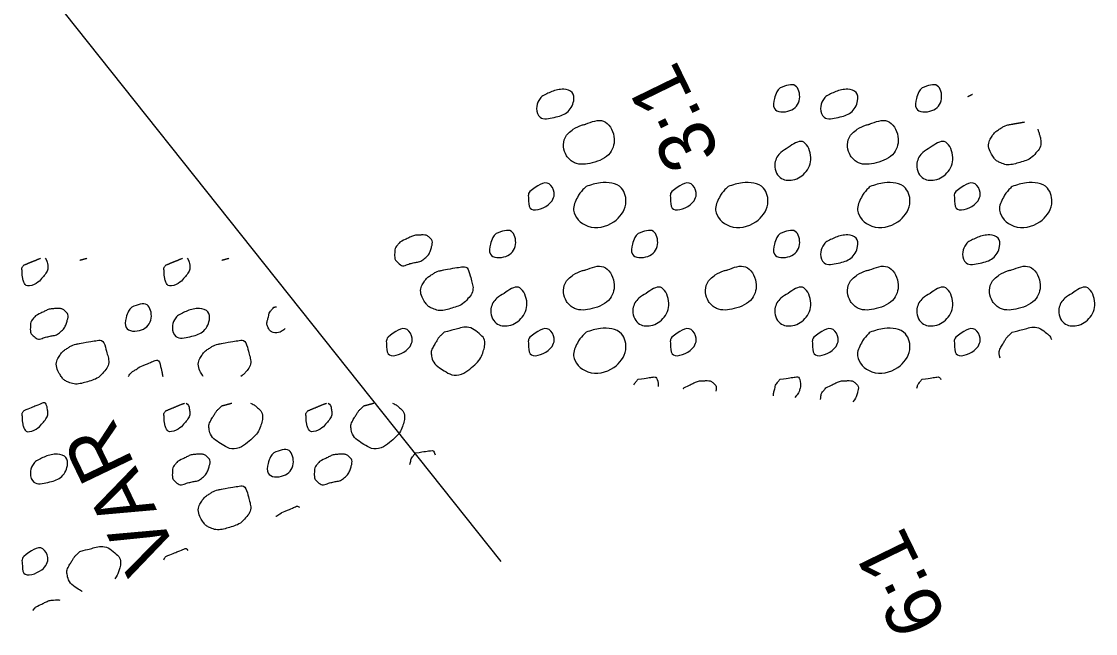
# Model space of a CAD drawing. Extents: x 0 to 2278, y -264 to 330.
# Drawn here: x 114.06 to 154.18, y 221.76 to 244.64 of the extents above; entities that cross this region are included whole.
import ezdxf

# ---------------------------------------------------------------- set-up
doc = ezdxf.new("R2010")
doc.units = 0
doc.layers.add('DR_P_Culvert', color=7, linetype='Continuous')
doc.layers.add('XS_P_Finished_Grade', color=7, linetype='Continuous')

msp = doc.modelspace()

# ---------------------------------------------------------------- linework, layer by layer
at = {"layer": 'DR_P_Culvert'}
msp.add_line((131.975, 224.45), (97.773, 267.515), dxfattribs=at)
at = {"layer": 'XS_P_Finished_Grade'}
for points in [[(142.395, 242.152), (142.967, 242.235), (143.124, 241.743), (142.764, 241.302), (142.184, 241.387), (142.187, 241.755), (142.275, 242), (142.395, 242.152)], [(147.699, 242.152), (148.271, 242.235), (148.427, 241.743), (148.067, 241.302), (147.487, 241.387), (147.491, 241.755), (147.579, 242), (147.699, 242.152)], [(133.494, 241.827), (133.869, 242.014), (134.32, 242.1), (134.636, 241.979), (134.688, 241.674), (134.431, 241.229), (133.961, 241.049), (133.434, 241.058), (133.305, 241.382), (133.383, 241.682), (133.494, 241.827)], [(144.101, 241.827), (144.476, 242.014), (144.927, 242.1), (145.244, 241.979), (145.295, 241.674), (145.039, 241.229), (144.569, 241.049), (144.041, 241.058), (143.912, 241.382), (143.99, 241.682), (144.101, 241.827)], [(135.124, 240.793), (135.805, 240.907), (136.194, 240.337), (136.049, 239.727), (135.38, 239.348), (134.72, 239.352), (134.421, 239.619), (134.366, 240.287), (134.674, 240.607), (135.013, 240.769), (135.136, 240.795)], [(145.731, 240.793), (146.412, 240.907), (146.801, 240.337), (146.656, 239.727), (145.987, 239.348), (145.327, 239.352), (145.029, 239.619), (144.974, 240.287), (145.281, 240.607), (145.62, 240.769), (145.744, 240.795)], [(142.701, 239.919), (143.229, 240.145), (143.54, 239.638), (143.372, 239.03), (142.872, 238.712), (142.406, 238.8), (142.206, 239.339), (142.425, 239.74), (142.701, 239.919)], [(148.005, 239.919), (148.532, 240.145), (148.844, 239.638), (148.676, 239.03), (148.176, 238.712), (147.71, 238.8), (147.51, 239.339), (147.729, 239.74), (148.005, 239.919)], [(133.056, 238.277), (133.769, 238.565), (133.958, 238.238), (133.734, 237.784), (133.059, 237.658), (133, 238.018), (133.006, 238.199), (133.056, 238.277)], [(135.155, 238.465), (135.689, 238.605), (136.47, 238.408), (136.631, 237.804), (136.188, 237.152), (135.215, 236.985), (134.684, 237.583), (134.826, 238.06), (135.034, 238.349), (135.155, 238.465)], [(138.36, 238.277), (139.072, 238.565), (139.261, 238.238), (139.037, 237.784), (138.362, 237.658), (138.304, 238.018), (138.31, 238.199), (138.36, 238.277)], [(140.459, 238.465), (140.992, 238.605), (141.774, 238.408), (141.935, 237.804), (141.491, 237.152), (140.519, 236.985), (139.987, 237.583), (140.13, 238.06), (140.337, 238.349), (140.459, 238.465)], [(145.762, 238.465), (146.296, 238.605), (147.077, 238.408), (147.239, 237.804), (146.795, 237.152), (145.822, 236.985), (145.291, 237.583), (145.434, 238.06), (145.641, 238.349), (145.762, 238.465)], [(148.967, 238.277), (149.68, 238.565), (149.869, 238.238), (149.645, 237.784), (148.97, 237.658), (148.911, 238.018), (148.917, 238.199), (148.967, 238.277)], [(151.066, 238.465), (151.6, 238.605), (152.381, 238.408), (152.542, 237.804), (152.099, 237.152), (151.126, 236.985), (150.595, 237.583), (150.737, 238.06), (150.945, 238.349), (151.066, 238.465)], [(131.788, 236.706), (132.36, 236.79), (132.516, 236.297), (132.156, 235.856), (131.576, 235.941), (131.58, 236.31), (131.668, 236.555), (131.788, 236.706)], [(137.091, 236.706), (137.664, 236.79), (137.82, 236.297), (137.46, 235.856), (136.88, 235.941), (136.884, 236.31), (136.971, 236.555), (137.091, 236.706)], [(142.395, 236.706), (142.967, 236.79), (143.124, 236.297), (142.764, 235.856), (142.184, 235.941), (142.187, 236.31), (142.275, 236.555), (142.395, 236.706)], [(144.101, 236.381), (144.476, 236.568), (144.927, 236.655), (145.244, 236.533), (145.295, 236.228), (145.039, 235.783), (144.569, 235.603), (144.041, 235.612), (143.912, 235.936), (143.99, 236.236), (144.101, 236.381)], [(149.405, 236.381), (149.78, 236.568), (150.231, 236.655), (150.547, 236.533), (150.599, 236.228), (150.342, 235.783), (149.872, 235.603), (149.345, 235.612), (149.216, 235.936), (149.294, 236.236), (149.405, 236.381)], [(135.124, 235.347), (135.805, 235.461), (136.194, 234.891), (136.049, 234.281), (135.38, 233.902), (134.72, 233.906), (134.421, 234.173), (134.366, 234.841), (134.674, 235.161), (135.013, 235.323), (135.136, 235.35)], [(140.427, 235.347), (141.109, 235.461), (141.497, 234.891), (141.352, 234.281), (140.684, 233.902), (140.024, 233.906), (139.725, 234.173), (139.67, 234.841), (139.977, 235.161), (140.316, 235.323), (140.44, 235.35)], [(145.731, 235.347), (146.412, 235.461), (146.801, 234.891), (146.656, 234.281), (145.987, 233.902), (145.327, 233.906), (145.029, 234.173), (144.974, 234.841), (145.281, 235.161), (145.62, 235.323), (145.744, 235.35)], [(151.035, 235.347), (151.716, 235.461), (152.105, 234.891), (151.96, 234.281), (151.291, 233.902), (150.631, 233.906), (150.332, 234.173), (150.277, 234.841), (150.585, 235.161), (150.924, 235.323), (151.047, 235.35)], [(132.094, 234.473), (132.621, 234.7), (132.933, 234.192), (132.765, 233.585), (132.265, 233.266), (131.799, 233.355), (131.599, 233.893), (131.818, 234.295), (132.094, 234.473)], [(137.398, 234.473), (137.925, 234.7), (138.236, 234.192), (138.069, 233.585), (137.569, 233.266), (137.103, 233.355), (136.903, 233.893), (137.121, 234.295), (137.398, 234.473)], [(142.701, 234.473), (143.229, 234.7), (143.54, 234.192), (143.372, 233.585), (142.872, 233.266), (142.406, 233.355), (142.206, 233.893), (142.425, 234.295), (142.701, 234.473)], [(148.005, 234.473), (148.532, 234.7), (148.844, 234.192), (148.676, 233.585), (148.176, 233.266), (147.71, 233.355), (147.51, 233.893), (147.729, 234.295), (148.005, 234.473)], [(153.309, 234.473), (153.836, 234.7), (154.147, 234.192), (153.98, 233.585), (153.48, 233.266), (153.014, 233.355), (152.814, 233.893), (153.032, 234.295), (153.309, 234.473)], [(118.18, 233.956), (118.753, 234.04), (118.909, 233.547), (118.549, 233.106), (117.969, 233.191), (117.973, 233.56), (118.06, 233.805), (118.18, 233.956)], [(119.886, 233.631), (120.261, 233.818), (120.713, 233.905), (121.029, 233.783), (121.08, 233.478), (120.824, 233.033), (120.354, 232.853), (119.826, 232.862), (119.698, 233.186), (119.775, 233.486), (119.886, 233.631)], [(127.753, 232.831), (128.465, 233.12), (128.654, 232.792), (128.43, 232.338), (127.755, 232.212), (127.696, 232.572), (127.703, 232.753), (127.753, 232.831)], [(133.056, 232.831), (133.769, 233.12), (133.958, 232.792), (133.734, 232.338), (133.059, 232.212), (133, 232.572), (133.006, 232.753), (133.056, 232.831)], [(135.155, 233.02), (135.689, 233.16), (136.47, 232.962), (136.631, 232.358), (136.188, 231.706), (135.215, 231.54), (134.684, 232.137), (134.826, 232.615), (135.034, 232.903), (135.155, 233.02)], [(138.36, 232.831), (139.072, 233.12), (139.261, 232.792), (139.037, 232.338), (138.362, 232.212), (138.304, 232.572), (138.31, 232.753), (138.36, 232.831)], [(143.664, 232.831), (144.376, 233.12), (144.565, 232.792), (144.341, 232.338), (143.666, 232.212), (143.607, 232.572), (143.614, 232.753), (143.664, 232.831)], [(145.762, 233.02), (146.296, 233.16), (147.077, 232.962), (147.239, 232.358), (146.795, 231.706), (145.822, 231.54), (145.291, 232.137), (145.434, 232.615), (145.641, 232.903), (145.762, 233.02)], [(148.967, 232.831), (149.68, 233.12), (149.869, 232.792), (149.645, 232.338), (148.97, 232.212), (148.911, 232.572), (148.917, 232.753), (148.967, 232.831)], [(123.484, 228.51), (124.056, 228.594), (124.213, 228.101), (123.853, 227.66), (123.273, 227.745), (123.276, 228.114), (123.364, 228.359), (123.484, 228.51)], [(114.583, 228.185), (114.958, 228.373), (115.409, 228.459), (115.725, 228.338), (115.776, 228.033), (115.52, 227.588), (115.05, 227.408), (114.523, 227.416), (114.394, 227.74), (114.471, 228.04), (114.583, 228.185)], [(114.145, 224.635), (114.858, 224.924), (115.046, 224.596), (114.823, 224.143), (114.148, 224.016), (114.089, 224.376), (114.095, 224.558), (114.145, 224.635)]]:
    msp.add_spline(points, degree=3, dxfattribs=at)
for points, degree in [([(149.405, 241.827), (149.465, 241.857), (149.526, 241.887), (149.587, 241.918)], 2), ([(152.019, 240.613), (152.057, 240.517), (152.084, 240.415), (152.105, 240.337), (152.157, 240.143), (152.123, 239.907), (151.96, 239.727), (151.76, 239.505), (151.538, 239.42), (151.291, 239.348), (151.079, 239.286), (150.842, 239.263), (150.631, 239.352), (150.503, 239.406), (150.41, 239.499), (150.332, 239.619), (150.203, 239.82), (150.164, 240.097), (150.277, 240.287), (150.352, 240.412), (150.454, 240.523), (150.585, 240.607), (150.696, 240.677), (150.801, 240.743), (150.924, 240.769), (150.965, 240.778), (151.006, 240.787), (151.047, 240.795)], 3), ([(151.035, 240.793), (151.198, 240.821), (151.362, 240.851), (151.526, 240.878)], 2), ([(128.19, 236.381), (128.315, 236.444), (128.44, 236.506), (128.565, 236.568), (128.702, 236.637), (128.867, 236.65), (129.016, 236.655), (129.127, 236.658), (129.233, 236.632), (129.333, 236.533), (129.423, 236.443), (129.41, 236.323), (129.384, 236.228), (129.339, 236.071), (129.281, 235.911), (129.128, 235.783), (128.977, 235.659), (128.819, 235.641), (128.658, 235.603), (128.489, 235.564), (128.295, 235.464), (128.13, 235.612), (128.021, 235.71), (127.998, 235.824), (128.001, 235.936), (128.004, 236.035), (128.016, 236.153), (128.079, 236.236), (128.116, 236.285), (128.153, 236.333), (128.19, 236.381)], 3), ([(114.949, 235.784), (115.007, 235.716), (115.039, 235.566), (115.046, 235.488), (115.06, 235.338), (114.946, 235.182), (114.823, 235.034), (114.655, 234.833), (114.234, 234.687), (114.148, 234.908), (114.101, 235.025), (114.094, 235.147), (114.089, 235.268), (114.086, 235.328), (114.064, 235.395), (114.095, 235.449), (114.111, 235.477), (114.129, 235.501), (114.145, 235.527)], 3), ([(114.145, 235.527), (114.356, 235.612), (114.567, 235.702), (114.777, 235.784)], 2), ([(116.244, 235.715), (116.331, 235.739), (116.418, 235.762), (116.505, 235.784)], 2), ([(120.252, 235.784), (120.311, 235.716), (120.343, 235.566), (120.35, 235.488), (120.364, 235.338), (120.25, 235.182), (120.126, 235.034), (119.959, 234.833), (119.538, 234.687), (119.451, 234.908), (119.405, 235.025), (119.397, 235.147), (119.393, 235.268), (119.39, 235.328), (119.367, 235.395), (119.399, 235.449), (119.415, 235.477), (119.432, 235.501), (119.449, 235.527)], 3), ([(119.449, 235.527), (119.66, 235.612), (119.87, 235.702), (120.081, 235.784)], 2), ([(121.548, 235.715), (121.635, 235.739), (121.722, 235.762), (121.809, 235.784)], 2), ([(129.82, 235.347), (130.047, 235.386), (130.274, 235.429), (130.501, 235.461), (130.728, 235.493), (130.833, 235.104), (130.89, 234.891), (130.942, 234.698), (130.908, 234.461), (130.745, 234.281), (130.545, 234.06), (130.323, 233.975), (130.076, 233.902), (129.864, 233.84), (129.627, 233.817), (129.416, 233.906), (129.288, 233.96), (129.195, 234.053), (129.118, 234.173), (128.988, 234.374), (128.949, 234.651), (129.063, 234.841), (129.138, 234.967), (129.239, 235.078), (129.37, 235.161), (129.481, 235.231), (129.586, 235.297), (129.709, 235.323), (129.75, 235.332), (129.791, 235.341), (129.833, 235.35)], 3), ([(114.583, 233.631), (114.707, 233.694), (114.832, 233.756), (114.958, 233.818), (115.095, 233.887), (115.259, 233.9), (115.409, 233.905), (115.519, 233.908), (115.626, 233.882), (115.725, 233.783), (115.816, 233.693), (115.803, 233.573), (115.776, 233.478), (115.732, 233.321), (115.673, 233.161), (115.52, 233.033), (115.37, 232.909), (115.211, 232.891), (115.05, 232.853), (114.881, 232.814), (114.688, 232.714), (114.523, 232.862), (114.413, 232.96), (114.391, 233.074), (114.394, 233.186), (114.396, 233.285), (114.409, 233.403), (114.471, 233.486), (114.508, 233.535), (114.545, 233.583), (114.583, 233.631)], 3), ([(123.913, 233.154), (123.893, 233.138), (123.873, 233.121), (123.853, 233.106), (123.695, 232.986), (123.364, 233.005), (123.273, 233.191), (123.215, 233.308), (123.244, 233.443), (123.276, 233.56), (123.299, 233.642), (123.31, 233.737), (123.364, 233.805), (123.404, 233.855), (123.444, 233.906), (123.484, 233.956)], 3), ([(123.484, 233.956), (123.521, 233.961), (123.557, 233.967), (123.594, 233.972)], 2), ([(129.851, 233.02), (130.029, 233.067), (130.207, 233.114), (130.385, 233.16), (130.645, 233.227), (130.906, 233.179), (131.166, 232.962), (131.368, 232.794), (131.381, 232.544), (131.328, 232.358), (131.26, 232.123), (131.112, 231.901), (130.884, 231.706), (130.599, 231.463), (130.203, 231.367), (129.911, 231.54), (129.675, 231.68), (129.426, 231.889), (129.38, 232.137), (129.352, 232.291), (129.432, 232.471), (129.523, 232.615), (129.587, 232.717), (129.645, 232.821), (129.73, 232.903), (129.77, 232.942), (129.811, 232.981), (129.851, 233.02)], 3), ([(151.066, 233.02), (151.244, 233.067), (151.422, 233.114), (151.6, 233.16), (151.86, 233.227), (152.121, 233.179), (152.381, 232.962), (152.455, 232.9), (152.504, 232.828), (152.533, 232.751)], 3), ([(116.213, 232.597), (116.439, 232.636), (116.667, 232.679), (116.894, 232.711), (117.121, 232.743), (117.226, 232.354), (117.283, 232.141), (117.334, 231.948), (117.301, 231.711), (117.138, 231.531), (116.938, 231.31), (116.715, 231.225), (116.469, 231.152), (116.257, 231.09), (116.02, 231.067), (115.809, 231.156), (115.681, 231.21), (115.588, 231.303), (115.51, 231.423), (115.38, 231.624), (115.342, 231.901), (115.455, 232.091), (115.53, 232.217), (115.632, 232.328), (115.763, 232.411), (115.873, 232.481), (115.979, 232.547), (116.101, 232.573), (116.143, 232.582), (116.184, 232.591), (116.225, 232.6)], 3), ([(121.516, 232.597), (121.743, 232.636), (121.971, 232.679), (122.198, 232.711), (122.424, 232.743), (122.529, 232.354), (122.586, 232.141), (122.638, 231.948), (122.604, 231.711), (122.441, 231.531), (122.382, 231.465), (122.321, 231.412), (122.258, 231.367)], 3), ([(150.618, 232.055), (150.608, 232.082), (150.6, 232.109), (150.595, 232.137), (150.567, 232.291), (150.647, 232.471), (150.737, 232.615), (150.802, 232.717), (150.86, 232.821), (150.945, 232.903), (150.985, 232.942), (151.026, 232.981), (151.066, 233.02)], 3), ([(120.853, 231.367), (120.839, 231.385), (120.826, 231.404), (120.814, 231.423), (120.684, 231.624), (120.646, 231.901), (120.759, 232.091), (120.834, 232.217), (120.936, 232.328), (121.066, 232.411), (121.177, 232.481), (121.283, 232.547), (121.405, 232.573), (121.446, 232.582), (121.488, 232.591), (121.529, 232.6)], 3), ([(118.486, 231.723), (118.662, 231.799), (118.838, 231.874), (119.014, 231.95), (119.196, 232.028), (119.285, 231.628), (119.325, 231.442), (119.33, 231.417), (119.334, 231.392), (119.337, 231.367)], 3), ([(118.065, 231.367), (118.1, 231.438), (118.147, 231.503), (118.21, 231.545), (118.302, 231.606), (118.394, 231.664), (118.486, 231.723)], 3), ([(136.939, 231.056), (136.948, 231.075), (136.958, 231.093), (136.971, 231.109), (137.011, 231.159), (137.051, 231.21), (137.091, 231.26)], 3), ([(137.091, 231.26), (137.282, 231.288), (137.473, 231.318), (137.664, 231.344), (137.794, 231.361), (137.848, 231.151), (137.842, 230.985)], 3), ([(138.797, 230.935), (138.922, 230.998), (139.047, 231.06), (139.172, 231.123), (139.31, 231.191), (139.474, 231.205), (139.624, 231.209), (139.734, 231.212), (139.84, 231.186), (139.94, 231.088), (140.021, 231.008), (140.02, 230.904), (140, 230.816)], 3), ([(142.151, 230.647), (142.151, 230.72), (142.168, 230.795), (142.187, 230.864), (142.21, 230.946), (142.221, 231.041), (142.275, 231.109), (142.315, 231.159), (142.355, 231.21), (142.395, 231.26)], 3), ([(142.395, 231.26), (142.586, 231.288), (142.777, 231.318), (142.967, 231.344), (143.138, 231.367), (143.178, 230.999), (143.124, 230.851), (143.09, 230.759), (143.028, 230.667), (142.953, 230.584)], 3), ([(144.101, 230.935), (144.226, 230.998), (144.351, 231.06), (144.476, 231.123), (144.614, 231.191), (144.778, 231.205), (144.927, 231.209), (145.038, 231.212), (145.144, 231.186), (145.244, 231.088), (145.335, 230.998), (145.322, 230.878), (145.295, 230.783), (145.259, 230.655), (145.214, 230.526), (145.117, 230.414)], 3), ([(147.506, 230.924), (147.522, 230.989), (147.538, 231.057), (147.579, 231.109), (147.619, 231.159), (147.659, 231.21), (147.699, 231.26)], 3), ([(147.699, 231.26), (147.89, 231.288), (148.08, 231.318), (148.271, 231.344), (148.331, 231.352), (148.375, 231.312), (148.404, 231.25)], 3), ([(138.779, 230.911), (138.785, 230.919), (138.791, 230.927), (138.797, 230.935)], 2), ([(143.913, 230.508), (143.917, 230.604), (143.931, 230.712), (143.99, 230.79), (144.027, 230.839), (144.064, 230.887), (144.101, 230.935)], 3), ([(114.145, 230.081), (114.383, 230.177), (114.62, 230.279), (114.858, 230.37), (114.974, 230.414), (115.036, 230.154), (115.046, 230.042), (115.06, 229.893), (114.946, 229.737), (114.823, 229.588), (114.655, 229.387), (114.234, 229.241), (114.148, 229.462), (114.101, 229.58), (114.094, 229.701), (114.089, 229.822), (114.086, 229.882), (114.064, 229.949), (114.095, 230.003), (114.111, 230.031), (114.129, 230.055), (114.145, 230.081)], 3), ([(120.218, 230.367), (120.298, 230.326), (120.341, 230.134), (120.35, 230.042), (120.364, 229.893), (120.25, 229.737), (120.126, 229.588), (119.959, 229.387), (119.538, 229.241), (119.451, 229.462), (119.405, 229.58), (119.397, 229.701), (119.393, 229.822), (119.39, 229.882), (119.367, 229.949), (119.399, 230.003), (119.415, 230.031), (119.432, 230.055), (119.449, 230.081)], 3), ([(119.449, 230.081), (119.684, 230.176), (119.919, 230.277), (120.154, 230.367)], 2), ([(122.62, 230.367), (122.701, 230.331), (122.782, 230.28), (122.863, 230.212), (123.064, 230.044), (123.077, 229.794), (123.024, 229.608), (122.956, 229.373), (122.808, 229.151), (122.58, 228.956), (122.295, 228.713), (121.899, 228.617), (121.608, 228.79), (121.371, 228.93), (121.122, 229.139), (121.076, 229.387), (121.048, 229.541), (121.128, 229.721), (121.219, 229.865), (121.283, 229.967), (121.341, 230.071), (121.426, 230.153), (121.467, 230.192), (121.507, 230.231), (121.548, 230.27)], 3), ([(121.548, 230.27), (121.671, 230.302), (121.794, 230.335), (121.917, 230.367)], 2), ([(125.522, 230.367), (125.602, 230.326), (125.645, 230.134), (125.654, 230.042), (125.668, 229.893), (125.553, 229.737), (125.43, 229.588), (125.263, 229.387), (124.842, 229.241), (124.755, 229.462), (124.709, 229.58), (124.701, 229.701), (124.696, 229.822), (124.694, 229.882), (124.671, 229.949), (124.703, 230.003), (124.718, 230.031), (124.736, 230.055), (124.753, 230.081)], 3), ([(124.753, 230.081), (124.988, 230.176), (125.223, 230.277), (125.458, 230.367)], 2), ([(127.924, 230.367), (128.005, 230.331), (128.086, 230.28), (128.166, 230.212), (128.368, 230.044), (128.381, 229.794), (128.328, 229.608), (128.26, 229.373), (128.112, 229.151), (127.884, 228.956), (127.599, 228.713), (127.203, 228.617), (126.911, 228.79), (126.675, 228.93), (126.426, 229.139), (126.38, 229.387), (126.352, 229.541), (126.432, 229.721), (126.523, 229.865), (126.587, 229.967), (126.645, 230.071), (126.73, 230.153), (126.77, 230.192), (126.811, 230.231), (126.851, 230.27)], 3), ([(126.851, 230.27), (126.974, 230.302), (127.098, 230.335), (127.221, 230.367)], 2), ([(119.886, 228.185), (120.011, 228.248), (120.136, 228.31), (120.261, 228.373), (120.399, 228.441), (120.563, 228.455), (120.713, 228.459), (120.823, 228.462), (120.929, 228.436), (121.029, 228.338), (121.12, 228.248), (121.107, 228.128), (121.08, 228.033), (121.036, 227.875), (120.977, 227.715), (120.824, 227.588), (120.674, 227.463), (120.515, 227.445), (120.354, 227.408), (120.185, 227.368), (119.991, 227.268), (119.826, 227.416), (119.717, 227.514), (119.695, 227.628), (119.698, 227.74), (119.7, 227.84), (119.712, 227.957), (119.775, 228.04), (119.812, 228.089), (119.849, 228.137), (119.886, 228.185)], 3), ([(125.19, 228.185), (125.315, 228.248), (125.44, 228.31), (125.565, 228.373), (125.702, 228.441), (125.867, 228.455), (126.016, 228.459), (126.127, 228.462), (126.233, 228.436), (126.333, 228.338), (126.423, 228.248), (126.41, 228.128), (126.384, 228.033), (126.339, 227.875), (126.281, 227.715), (126.128, 227.588), (125.977, 227.463), (125.819, 227.445), (125.658, 227.408), (125.489, 227.368), (125.295, 227.268), (125.13, 227.416), (125.021, 227.514), (124.998, 227.628), (125.001, 227.74), (125.004, 227.84), (125.016, 227.957), (125.079, 228.04), (125.116, 228.089), (125.153, 228.137), (125.19, 228.185)], 3), ([(128.569, 228.072), (128.572, 228.086), (128.576, 228.1), (128.58, 228.114), (128.603, 228.196), (128.614, 228.291), (128.668, 228.359), (128.707, 228.409), (128.747, 228.46), (128.788, 228.51)], 3), ([(128.788, 228.51), (128.978, 228.538), (129.169, 228.568), (129.36, 228.594), (129.438, 228.604), (129.488, 228.533), (129.515, 228.439)], 3), ([(121.516, 227.151), (121.743, 227.19), (121.971, 227.233), (122.198, 227.265), (122.424, 227.297), (122.529, 226.908), (122.586, 226.695), (122.638, 226.502), (122.604, 226.266), (122.441, 226.085), (122.241, 225.864), (122.019, 225.779), (121.773, 225.706), (121.561, 225.644), (121.323, 225.621), (121.113, 225.71), (120.984, 225.764), (120.891, 225.857), (120.814, 225.978), (120.684, 226.179), (120.646, 226.455), (120.759, 226.645), (120.834, 226.771), (120.936, 226.882), (121.066, 226.965), (121.177, 227.036), (121.283, 227.102), (121.405, 227.128), (121.446, 227.136), (121.488, 227.145), (121.529, 227.154)], 3), ([(123.568, 226.135), (123.642, 226.183), (123.716, 226.23), (123.79, 226.278)], 2), ([(123.79, 226.278), (123.966, 226.353), (124.142, 226.428), (124.318, 226.504), (124.367, 226.525), (124.41, 226.511), (124.447, 226.475)], 3), ([(116.329, 223.33), (116.32, 223.334), (116.312, 223.339), (116.304, 223.344), (116.067, 223.484), (115.818, 223.694), (115.773, 223.941), (115.744, 224.096), (115.824, 224.275), (115.915, 224.419), (115.98, 224.521), (116.037, 224.625), (116.123, 224.708), (116.163, 224.747), (116.203, 224.785), (116.244, 224.824)], 3), ([(116.244, 224.824), (116.422, 224.871), (116.6, 224.918), (116.778, 224.964), (117.037, 225.031), (117.299, 224.984), (117.559, 224.766), (117.76, 224.598), (117.773, 224.349), (117.72, 224.163), (117.684, 224.038), (117.626, 223.916), (117.544, 223.801)], 3), ([(119.449, 224.635), (119.686, 224.731), (119.924, 224.833), (120.161, 224.924), (120.208, 224.942), (120.246, 224.91), (120.276, 224.859)], 3), ([(119.384, 224.514), (119.386, 224.529), (119.391, 224.544), (119.399, 224.558), (119.415, 224.585), (119.432, 224.609), (119.449, 224.635)], 3), ([(114.488, 222.617), (114.52, 222.658), (114.551, 222.699), (114.583, 222.739)], 2), ([(114.583, 222.739), (114.707, 222.802), (114.832, 222.865), (114.958, 222.927), (115.095, 222.995), (115.259, 223.009), (115.409, 223.013), (115.439, 223.014), (115.469, 223.013), (115.499, 223.008)], 3)]:
    msp.add_open_spline(points, degree=degree, dxfattribs=at)

# ---------------------------------------------------------------- texts
at = {"layer": 'DR_P_Culvert'}
for s, rotation, p in [('3:1', 115.9839, (140.197, 239.714)), ('VAR', 115.6557, (119.937, 224.685)), ('6:1', 115.9839, (148.681, 222.306))]:
    msp.add_text(s, height=2.1, rotation=rotation, dxfattribs=at).set_placement(p)

doc.saveas('drawing.dxf')
